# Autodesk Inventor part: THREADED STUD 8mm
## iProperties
Created: 2007-03
Part Number: THREADED STUD 8mm
Document SubType Name: Modeling
Designer: Andy Moles
Material: Steel
Mass: 40.6007 g
Surface Area: 22.6004 cm^2
Volume: 5.17207 cm^3
Density: 7.85 g/cm^3
Author: Andy Moles
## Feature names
1. Revolution1
2. Extrusion1
3. Extrusion2
4. Extrusion3
5. Chamfer1
